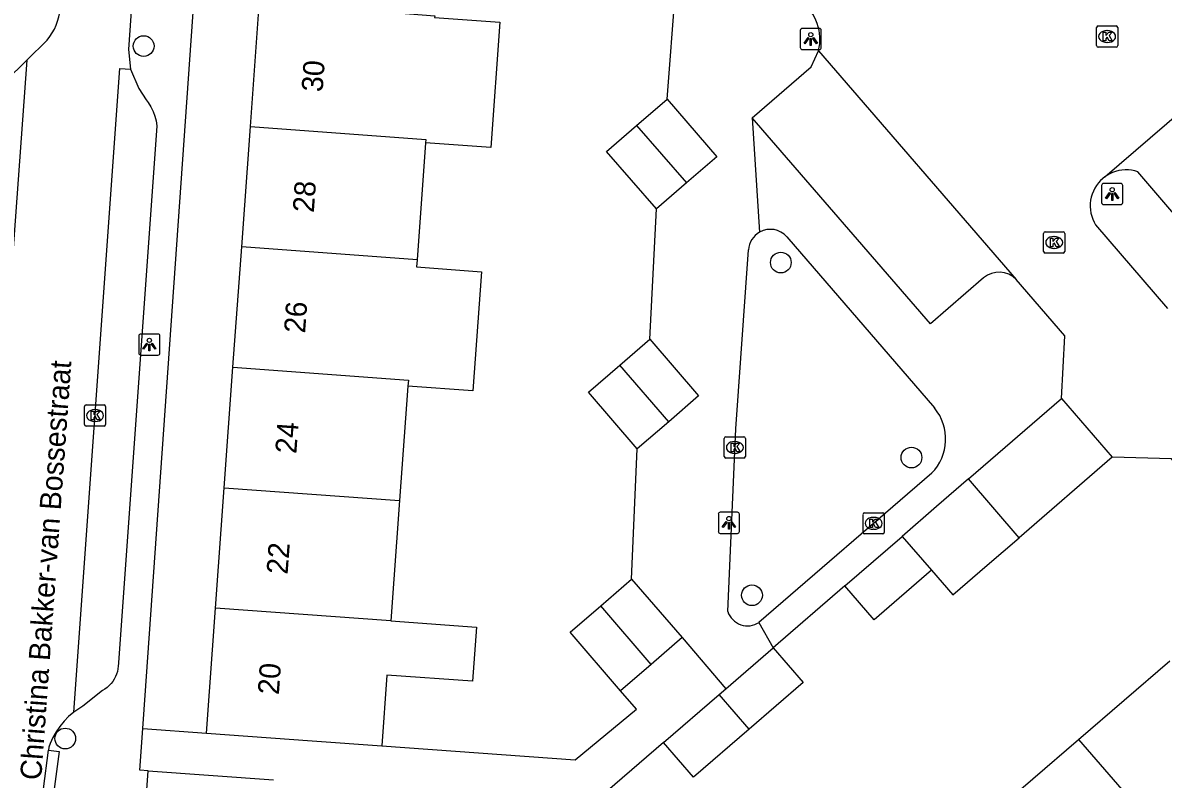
# Model space of a CAD drawing. Extents: x 160304 to 160954, y 383686 to 384161.
# Drawn here: x 160524.6 to 160578.4, y 384061.9 to 384097.6 of the extents above; entities that cross this region are included whole.
import ezdxf

# ---------------------------------------------------------------- set-up
doc = ezdxf.new("R2010")
doc.units = 0
for name, color, linetype in [('IMGEO_Boom', 7, 'Continuous'), ('IMGEO_Kolk', 7, 'Continuous'), ('IMGEO_Lichtpunt', 7, 'Continuous'), ('IMGEO_Openbare_ruimte_label', 7, 'Continuous'), ('IMGEO_Pand', 7, 'Continuous'), ('IMGEO_Pand_nummerreeks', 7, 'Continuous'), ('IMGEO_Rijbaan_lokaal_open', 7, 'Continuous'), ('IMGEO_Voetpad_open', 7, 'Continuous')]:
    doc.layers.add(name, color=color, linetype=linetype)

msp = doc.modelspace()

# ---------------------------------------------------------------- linework, layer by layer
at = {"layer": 'IMGEO_Boom'}
for centre in [(160530.268, 384096.536), (160560.354, 384086.312), (160566.522, 384077.105), (160558.992, 384070.601), (160526.565, 384063.838)]:
    msp.add_circle(centre, 0.489, dxfattribs=at)
at = {"layer": 'IMGEO_Kolk'}
for p, q in [((160575.26, 384096.559), (160575.26, 384097.411)), ((160575.335, 384097.485), (160576.187, 384097.485)), ((160575.748, 384097.265), (160575.773, 384097.265)), ((160576.261, 384097.411), (160576.261, 384096.559)), ((160575.771, 384096.705), (160575.746, 384096.705)), ((160576.187, 384096.485), (160575.335, 384096.485)), ((160572.761, 384086.836), (160572.761, 384087.688)), ((160572.836, 384087.762), (160573.688, 384087.762)), ((160573.249, 384087.542), (160573.274, 384087.542)), ((160573.762, 384087.688), (160573.762, 384086.836)), ((160573.272, 384086.982), (160573.247, 384086.982)), ((160573.688, 384086.762), (160572.836, 384086.762)), ((160527.473, 384078.664), (160527.473, 384079.516)), ((160527.548, 384079.59), (160528.4, 384079.59)), ((160527.961, 384079.37), (160527.986, 384079.37)), ((160528.474, 384079.516), (160528.474, 384078.664)), ((160527.984, 384078.81), (160527.959, 384078.81)), ((160528.4, 384078.59), (160527.548, 384078.59)), ((160557.683, 384077.156), (160557.683, 384078.008)), ((160557.758, 384078.082), (160558.61, 384078.082)), ((160558.171, 384077.862), (160558.196, 384077.862)), ((160558.684, 384078.008), (160558.684, 384077.156)), ((160558.194, 384077.302), (160558.169, 384077.302)), ((160558.61, 384077.082), (160557.758, 384077.082)), ((160564.311, 384074.498), (160565.163, 384074.498)), ((160564.236, 384073.572), (160564.236, 384074.424)), ((160564.724, 384074.278), (160564.749, 384074.278)), ((160565.237, 384074.424), (160565.237, 384073.572)), ((160565.163, 384073.498), (160564.311, 384073.498)), ((160564.747, 384073.718), (160564.722, 384073.718))]:
    msp.add_line(p, q, dxfattribs=at)
for points in [[(160575.26, 384096.559), (160575.26, 384097.411)], [(160575.335, 384097.485), (160576.187, 384097.485)], [(160575.581, 384097.185), (160575.704, 384097.185), (160575.704, 384097.034), (160575.834, 384097.185), (160575.998, 384097.185), (160575.852, 384097.034), (160576.005, 384096.785), (160575.853, 384096.785), (160575.768, 384096.949), (160575.704, 384096.882), (160575.704, 384096.785), (160575.581, 384096.785), (160575.581, 384097.185)], [(160576.261, 384097.411), (160576.261, 384096.559)], [(160576.187, 384096.485), (160575.335, 384096.485)], [(160572.761, 384086.836), (160572.761, 384087.688)], [(160572.836, 384087.762), (160573.688, 384087.762)], [(160573.082, 384087.462), (160573.205, 384087.462), (160573.205, 384087.311), (160573.335, 384087.462), (160573.499, 384087.462), (160573.353, 384087.311), (160573.506, 384087.062), (160573.354, 384087.062), (160573.269, 384087.226), (160573.205, 384087.159), (160573.205, 384087.062), (160573.082, 384087.062), (160573.082, 384087.462)], [(160573.762, 384087.688), (160573.762, 384086.836)], [(160573.688, 384086.762), (160572.836, 384086.762)], [(160527.473, 384078.664), (160527.473, 384079.516)], [(160527.548, 384079.59), (160528.4, 384079.59)], [(160528.474, 384079.516), (160528.474, 384078.664)], [(160527.794, 384079.29), (160527.917, 384079.29), (160527.917, 384079.139), (160528.047, 384079.29), (160528.211, 384079.29), (160528.065, 384079.139), (160528.218, 384078.89), (160528.066, 384078.89), (160527.981, 384079.054), (160527.917, 384078.987), (160527.917, 384078.89), (160527.794, 384078.89), (160527.794, 384079.29)], [(160528.4, 384078.59), (160527.548, 384078.59)], [(160557.683, 384077.156), (160557.683, 384078.008)], [(160557.758, 384078.082), (160558.61, 384078.082)], [(160558.004, 384077.782), (160558.127, 384077.782), (160558.127, 384077.631), (160558.257, 384077.782), (160558.421, 384077.782), (160558.275, 384077.631), (160558.428, 384077.382), (160558.276, 384077.382), (160558.191, 384077.546), (160558.127, 384077.479), (160558.127, 384077.382), (160558.004, 384077.382), (160558.004, 384077.782)], [(160558.684, 384078.008), (160558.684, 384077.156)], [(160558.61, 384077.082), (160557.758, 384077.082)], [(160564.311, 384074.498), (160565.163, 384074.498)], [(160564.236, 384073.572), (160564.236, 384074.424)], [(160564.557, 384074.198), (160564.68, 384074.198), (160564.68, 384074.047), (160564.81, 384074.198), (160564.974, 384074.198), (160564.828, 384074.047), (160564.981, 384073.798), (160564.829, 384073.798), (160564.744, 384073.962), (160564.68, 384073.895), (160564.68, 384073.798), (160564.557, 384073.798), (160564.557, 384074.198)], [(160565.237, 384074.424), (160565.237, 384073.572)], [(160565.163, 384073.498), (160564.311, 384073.498)]]:
    msp.add_lwpolyline(points, dxfattribs=at)
for centre, start, end in [((160575.337, 384097.409), 91.552, 178.448), ((160575.337, 384097.409), 91.552, 178.448), ((160576.185, 384097.409), 1.552, 88.448), ((160576.185, 384097.409), 1.552, 88.448), ((160575.337, 384096.561), 181.552, 268.448), ((160575.337, 384096.561), 181.552, 268.448), ((160576.185, 384096.561), 271.552, 358.448), ((160576.185, 384096.561), 271.552, 358.448), ((160572.838, 384087.686), 91.552, 178.448), ((160572.838, 384087.686), 91.552, 178.448), ((160573.686, 384087.686), 1.552, 88.448), ((160573.686, 384087.686), 1.552, 88.448), ((160572.838, 384086.838), 181.552, 268.448), ((160572.838, 384086.838), 181.552, 268.448), ((160573.686, 384086.838), 271.552, 358.448), ((160573.686, 384086.838), 271.552, 358.448), ((160527.55, 384079.514), 91.552, 178.448), ((160527.55, 384079.514), 91.552, 178.448), ((160528.398, 384079.514), 1.552, 88.448), ((160528.398, 384079.514), 1.552, 88.448), ((160527.55, 384078.666), 181.552, 268.448), ((160527.55, 384078.666), 181.552, 268.448), ((160528.398, 384078.666), 271.552, 358.448), ((160528.398, 384078.666), 271.552, 358.448), ((160557.76, 384078.006), 91.552, 178.448), ((160557.76, 384078.006), 91.552, 178.448), ((160558.608, 384078.006), 1.552, 88.448), ((160558.608, 384078.006), 1.552, 88.448), ((160557.76, 384077.158), 181.552, 268.448), ((160557.76, 384077.158), 181.552, 268.448), ((160558.608, 384077.158), 271.552, 358.448), ((160558.608, 384077.158), 271.552, 358.448), ((160564.313, 384074.422), 91.552, 178.448), ((160564.313, 384074.422), 91.552, 178.448), ((160565.161, 384074.422), 1.552, 88.448), ((160565.161, 384074.422), 1.552, 88.448), ((160564.313, 384073.574), 181.552, 268.448), ((160564.313, 384073.574), 181.552, 268.448), ((160565.161, 384073.574), 271.552, 358.448), ((160565.161, 384073.574), 271.552, 358.448)]:
    msp.add_arc(centre, 0.0765, start, end, dxfattribs=at)
for centre, major_axis, ratio, start_param, end_param in [((160575.747, 384096.985), (-0.387, 0.002), 0.722429, 4.712389, 7.853982), ((160575.772, 384096.985), (-0.39, 0.002), 0.717154, 1.570796, 4.712389), ((160573.248, 384087.262), (-0.387, 0.002), 0.722429, 4.712389, 7.853982), ((160573.273, 384087.262), (-0.39, 0.002), 0.717154, 1.570796, 4.712389), ((160527.96, 384079.09), (-0.387, 0.002), 0.722429, 4.712389, 7.853982), ((160527.985, 384079.09), (-0.39, 0.002), 0.717154, 1.570796, 4.712389), ((160558.17, 384077.582), (-0.387, 0.002), 0.722429, 4.712389, 7.853982), ((160558.195, 384077.582), (-0.39, 0.002), 0.717154, 1.570796, 4.712389), ((160564.723, 384073.998), (-0.387, 0.002), 0.722429, 4.712389, 7.853982), ((160564.748, 384073.998), (-0.39, 0.002), 0.717154, 1.570796, 4.712389)]:
    msp.add_ellipse(centre, major_axis=major_axis, ratio=ratio, start_param=start_param, end_param=end_param, dxfattribs=at)
at = {"layer": 'IMGEO_Lichtpunt'}
for p, q in [((160561.269, 384097.274), (160561.269, 384096.467)), ((160561.269, 384097.274), (160561.269, 384096.467)), ((160562.171, 384097.369), (160561.363, 384097.369)), ((160562.171, 384097.369), (160561.363, 384097.369)), ((160562.265, 384096.467), (160562.265, 384097.274)), ((160562.265, 384096.467), (160562.265, 384097.274)), ((160561.363, 384096.373), (160562.171, 384096.373)), ((160561.363, 384096.373), (160562.171, 384096.373)), ((160575.501, 384089.953), (160575.501, 384089.146)), ((160575.501, 384089.953), (160575.501, 384089.146)), ((160576.403, 384090.048), (160575.595, 384090.048)), ((160576.403, 384090.048), (160575.595, 384090.048)), ((160576.497, 384089.146), (160576.497, 384089.953)), ((160576.497, 384089.146), (160576.497, 384089.953)), ((160575.595, 384089.052), (160576.403, 384089.052)), ((160575.595, 384089.052), (160576.403, 384089.052)), ((160530.04, 384082.844), (160530.04, 384082.037)), ((160530.04, 384082.844), (160530.04, 384082.037)), ((160530.942, 384082.939), (160530.134, 384082.939)), ((160530.942, 384082.939), (160530.134, 384082.939)), ((160531.036, 384082.037), (160531.036, 384082.844)), ((160531.036, 384082.037), (160531.036, 384082.844)), ((160530.134, 384081.943), (160530.942, 384081.943)), ((160530.134, 384081.943), (160530.942, 384081.943)), ((160558.305, 384074.521), (160557.497, 384074.521)), ((160558.305, 384074.521), (160557.497, 384074.521)), ((160557.403, 384074.426), (160557.403, 384073.619)), ((160557.403, 384074.426), (160557.403, 384073.619)), ((160558.399, 384073.619), (160558.399, 384074.426)), ((160558.399, 384073.619), (160558.399, 384074.426)), ((160557.497, 384073.525), (160558.305, 384073.525)), ((160557.497, 384073.525), (160558.305, 384073.525))]:
    msp.add_line(p, q, dxfattribs=at)
for points in [[(160561.643, 384096.938), (160561.682, 384096.91), (160561.494, 384096.648), (160561.456, 384096.675), (160561.643, 384096.938)], [(160561.745, 384096.89), (160561.792, 384096.89), (160561.792, 384096.568), (160561.745, 384096.568), (160561.745, 384096.89)], [(160561.855, 384096.91), (160561.893, 384096.937), (160562.08, 384096.675), (160562.041, 384096.647), (160561.855, 384096.91)], [(160575.875, 384089.617), (160575.914, 384089.589), (160575.726, 384089.327), (160575.688, 384089.354), (160575.875, 384089.617)], [(160575.977, 384089.569), (160576.024, 384089.569), (160576.024, 384089.247), (160575.977, 384089.247), (160575.977, 384089.569)], [(160576.087, 384089.589), (160576.125, 384089.616), (160576.312, 384089.354), (160576.273, 384089.326), (160576.087, 384089.589)], [(160530.414, 384082.508), (160530.453, 384082.48), (160530.265, 384082.218), (160530.227, 384082.245), (160530.414, 384082.508)], [(160530.516, 384082.46), (160530.563, 384082.46), (160530.563, 384082.138), (160530.516, 384082.138), (160530.516, 384082.46)], [(160530.626, 384082.48), (160530.664, 384082.507), (160530.851, 384082.245), (160530.812, 384082.217), (160530.626, 384082.48)], [(160557.777, 384074.09), (160557.816, 384074.062), (160557.628, 384073.8), (160557.59, 384073.827), (160557.777, 384074.09)], [(160557.879, 384074.042), (160557.926, 384074.042), (160557.926, 384073.72), (160557.879, 384073.72), (160557.879, 384074.042)], [(160557.989, 384074.062), (160558.027, 384074.089), (160558.214, 384073.827), (160558.175, 384073.799), (160557.989, 384074.062)]]:
    msp.add_lwpolyline(points, dxfattribs=at)
for centre in [(160561.768, 384097.072), (160576, 384089.751), (160530.539, 384082.642), (160557.902, 384074.224)]:
    msp.add_circle(centre, 0.0994, dxfattribs=at)
for centre, start, end in [((160561.363, 384097.274), 90, 180), ((160561.363, 384097.274), 90, 180), ((160562.171, 384097.274), 0, 90), ((160562.171, 384097.274), 0, 90), ((160561.363, 384096.467), 180, 270), ((160561.363, 384096.467), 180, 270), ((160562.171, 384096.467), 270, 0), ((160562.171, 384096.467), 270, 360), ((160575.595, 384089.953), 90, 180), ((160575.595, 384089.953), 90, 180), ((160576.403, 384089.953), 0, 90), ((160576.403, 384089.953), 0, 90), ((160575.595, 384089.146), 180, 270), ((160575.595, 384089.146), 180, 270), ((160576.403, 384089.146), 270, 0), ((160576.403, 384089.146), 270, 360), ((160530.134, 384082.844), 90, 180), ((160530.134, 384082.844), 90, 180), ((160530.942, 384082.844), 0, 90), ((160530.942, 384082.844), 0, 90), ((160530.134, 384082.037), 180, 270), ((160530.134, 384082.037), 180, 270), ((160530.942, 384082.037), 270, 0), ((160530.942, 384082.037), 270, 360), ((160557.497, 384074.426), 90, 180), ((160557.497, 384074.426), 90, 180), ((160558.305, 384074.426), 0, 90), ((160558.305, 384074.426), 0, 90), ((160557.497, 384073.619), 180, 270), ((160557.497, 384073.619), 180, 270), ((160558.305, 384073.619), 270, 0), ((160558.305, 384073.619), 270, 360)]:
    msp.add_arc(centre, 0.0946, start, end, dxfattribs=at)
at = {"layer": 'IMGEO_Pand'}
for points in [[(160535.311, 384092.74), (160535.71, 384098.248)], [(160541.621, 384098.144), (160544.014, 384097.97), (160544.008, 384097.884), (160547.083, 384097.661), (160546.654, 384091.741), (160543.578, 384091.964)], [(160553.542, 384092.781), (160554.982, 384094.025)], [(160554.982, 384094.025), (160557.328, 384091.308), (160555.899, 384090.074)], [(160554.476, 384088.845), (160552.13, 384091.562), (160553.542, 384092.781)], [(160553.542, 384092.781), (160555.899, 384090.074)], [(160534.898, 384087.058), (160535.311, 384092.74)], [(160535.311, 384092.74), (160543.59, 384092.131), (160543.578, 384091.964)], [(160543.578, 384091.964), (160543.178, 384086.442)], [(160555.899, 384090.074), (160554.476, 384088.845)], [(160534.486, 384081.371), (160534.898, 384087.058)], [(160543.178, 384086.442), (160534.898, 384087.058)], [(160543.178, 384086.442), (160543.157, 384086.103), (160546.216, 384085.882), (160545.808, 384080.251), (160542.745, 384080.473)], [(160552.746, 384081.463), (160554.164, 384082.688)], [(160554.164, 384082.688), (160556.472, 384080.015), (160555.058, 384078.794)], [(160534.073, 384075.671), (160534.486, 384081.371)], [(160534.486, 384081.371), (160542.766, 384080.763), (160542.745, 384080.473)], [(160553.577, 384077.515), (160551.269, 384080.187), (160552.746, 384081.463)], [(160555.058, 384078.794), (160552.746, 384081.463)], [(160542.745, 384080.473), (160542.354, 384075.083)], [(160569.209, 384076.095), (160573.604, 384079.891)], [(160573.604, 384079.891), (160575.999, 384077.117)], [(160555.058, 384078.794), (160553.577, 384077.515)], [(160575.999, 384077.117), (160571.605, 384073.322)], [(160569.209, 384076.095), (160567.7, 384074.792), (160566.086, 384073.383)], [(160571.605, 384073.322), (160569.209, 384076.095)], [(160533.66, 384069.988), (160534.073, 384075.671)], [(160534.073, 384075.671), (160542.354, 384075.083)], [(160542.354, 384075.083), (160541.941, 384069.389)], [(160563.378, 384071.043), (160566.086, 384073.383)], [(160566.086, 384073.383), (160567.462, 384071.789)], [(160567.462, 384071.789), (160568.473, 384070.617), (160570.095, 384072.018), (160571.605, 384073.322)], [(160567.462, 384071.789), (160564.754, 384069.45), (160563.378, 384071.043)], [(160551.854, 384070.104), (160553.309, 384071.36)], [(160553.309, 384071.36), (160555.691, 384068.602)], [(160533.233, 384064.096), (160533.66, 384069.988)], [(160541.941, 384069.389), (160533.66, 384069.988)], [(160552.791, 384066.097), (160550.409, 384068.856), (160551.854, 384070.104)], [(160554.225, 384067.336), (160551.854, 384070.104)], [(160541.941, 384069.389), (160545.981, 384069.097), (160545.796, 384066.543), (160541.756, 384066.836), (160541.514, 384063.495)], [(160555.691, 384068.602), (160554.225, 384067.336)], [(160557.754, 384066.187), (160559.998, 384068.125)], [(160559.998, 384068.125), (160561.414, 384066.485), (160558.864, 384064.283)], [(160574.41, 384063.793), (160578.719, 384067.513)], [(160554.225, 384067.336), (160552.791, 384066.097)], [(160554.82, 384063.652), (160557.438, 384065.914)], [(160557.438, 384065.914), (160557.754, 384066.187)], [(160558.864, 384064.283), (160557.438, 384065.914)], [(160558.864, 384064.283), (160556.236, 384062.013), (160554.82, 384063.652)], [(160533.233, 384064.096), (160538.22, 384063.734), (160541.514, 384063.495)], [(160570.102, 384060.072), (160574.41, 384063.793)], [(160574.41, 384063.793), (160579.845, 384057.535)], [(160530.229, 384058.743), (160530.488, 384062.32)], [(160530.488, 384062.32), (160536.399, 384061.891)]]:
    msp.add_lwpolyline(points, dxfattribs=at)
at = {"layer": 'IMGEO_Rijbaan_lokaal_open'}
for points in [[(160537.481, 384138.035), (160534.196, 384135.168), (160533.788, 384134.809), (160533.414, 384134.416), (160533.076, 384133.99), (160532.778, 384133.536), (160532.521, 384133.058), (160532.308, 384132.558), (160532.141, 384132.041), (160532.021, 384131.511), (160531.948, 384130.973), (160531.927, 384130.626), (160529.545, 384096.378), (160529.643, 384095.449)], [(160575.655, 384090.36), (160587.929, 384100.937)], [(160524.75, 384095.864), (160525.716, 384096.815)], [(160562.131, 384096.314), (160571.467, 384085.506)], [(160524.75, 384095.864), (160522.403, 384063.785)], [(160526.965, 384065.079), (160529.151, 384095.469), (160529.643, 384095.449)], [(160575.655, 384090.36), (160575.452, 384090.185), (160575.35, 384090.073), (160575.259, 384089.951), (160575.178, 384089.823), (160575.11, 384089.687), (160575.054, 384089.546), (160575.011, 384089.401), (160574.981, 384089.252), (160574.964, 384089.101), (160574.961, 384088.949), (160574.971, 384088.798), (160574.995, 384088.648), (160575.033, 384088.501), (160575.083, 384088.358), (160575.146, 384088.22), (160575.218, 384088.092), (160578.615, 384084.142)], [(160573.604, 384079.891), (160573.757, 384082.855), (160571.467, 384085.506)], [(160590.891, 384063.065), (160578.802, 384077.039), (160575.999, 384077.117)], [(160526.965, 384065.079), (160526.727, 384064.877), (160526.509, 384064.654), (160526.311, 384064.412), (160526.136, 384064.154), (160525.984, 384063.882), (160525.858, 384063.596), (160525.798, 384063.432), (160525.778, 384063.283)], [(160525.298, 384059.629), (160525.778, 384063.283)]]:
    msp.add_lwpolyline(points, dxfattribs=at)
for centre, radius, start, end in [((160523.525, 384098.596), 2.824, 320.8869, 354.3452), ((160559.948, 384096.863), 2.251, 345.8903, 52.6046)]:
    msp.add_arc(centre, radius, start, end, dxfattribs=at)
at = {"layer": 'IMGEO_Voetpad_open'}
for points in [[(160530.227, 384064.308), (160532.622, 384098.352), (160530.921, 384098.428), (160533.173, 384130.684), (160533.182, 384130.784), (160533.255, 384131.273), (160533.37, 384131.754), (160533.529, 384132.222), (160533.728, 384132.674), (160533.967, 384133.107), (160534.244, 384133.516), (160534.556, 384133.899), (160534.901, 384134.253), (160548.216, 384145.882), (160548.855, 384146.134)], [(160587.929, 384100.937), (160590.827, 384097.546), (160579.575, 384087.85), (160577.208, 384090.597), (160577.062, 384090.64), (160576.914, 384090.669), (160576.763, 384090.685), (160576.611, 384090.688), (160576.46, 384090.677), (160576.31, 384090.652), (160576.163, 384090.615), (160576.02, 384090.564), (160575.882, 384090.501), (160575.75, 384090.425), (160575.655, 384090.36)], [(160554.982, 384094.025), (160555.383, 384099.177)], [(160559.002, 384093.154), (160561.779, 384095.553), (160562.131, 384096.314)], [(160523.578, 384094.74), (160523.746, 384094.883), (160524.75, 384095.864)], [(160529.643, 384095.449), (160530.04, 384094.53), (160530.394, 384094.002), (160530.485, 384093.872), (160530.607, 384093.667), (160530.71, 384093.451), (160530.793, 384093.227), (160530.856, 384092.997), (160530.898, 384092.762), (160529.075, 384067.418), (160529.076, 384067.391), (160529.071, 384067.261), (160529.056, 384067.132), (160529.028, 384067.005), (160528.99, 384066.881), (160528.94, 384066.761), (160528.88, 384066.645), (160528.81, 384066.536), (160528.731, 384066.433), (160528.642, 384066.338), (160528.546, 384066.251), (160528.442, 384066.172), (160528.331, 384066.104), (160527.396, 384065.366), (160526.965, 384065.079)], [(160569.927, 384085.584), (160567.416, 384083.414), (160559.002, 384093.154)], [(160559.002, 384093.154), (160559.351, 384087.746)], [(160554.164, 384082.688), (160554.476, 384088.845)], [(160560.637, 384087.524), (160567.613, 384079.447)], [(160557.847, 384069.834), (160558.223, 384078.458), (160558.834, 384086.916)], [(160553.309, 384071.36), (160553.577, 384077.515)], [(160567.476, 384076.364), (160559.323, 384069.323)], [(160563.378, 384071.043), (160559.998, 384068.125)], [(160559.323, 384069.323), (160559.998, 384068.125)], [(160555.691, 384068.602), (160557.754, 384066.187)], [(160541.514, 384063.495), (160550.645, 384062.832), (160553.546, 384065.222), (160552.791, 384066.097)], [(160530.488, 384062.32), (160530.089, 384062.351), (160530.227, 384064.308)], [(160530.227, 384064.308), (160533.233, 384064.096)], [(160525.778, 384063.283), (160526.273, 384063.218), (160525.793, 384059.564), (160525.298, 384059.629)], [(160554.82, 384063.652), (160551.361, 384060.677), (160549.71, 384060.797)]]:
    msp.add_lwpolyline(points, dxfattribs=at)
for centre, radius, start, end in [((160559.855, 384086.856), 1.023, 119.5216, 176.6416), ((160559.859, 384086.855), 1.026, 40.7187, 119.6927), ((160570.657, 384084.751), 1.108, 42.9841, 131.2168), ((160565.816, 384077.982), 2.318, 315.7286, 39.1827), ((160558.78, 384070.14), 0.982, 198.1915, 303.6162)]:
    msp.add_arc(centre, radius, start, end, dxfattribs=at)

# ---------------------------------------------------------------- texts
at = {"layer": 'IMGEO_Openbare_ruimte_label'}
msp.add_text('Christina Bakker-van Bossestraat', height=1, rotation=85.8695, dxfattribs=at).set_placement((160525.427, 384061.851))
at = {"layer": 'IMGEO_Pand_nummerreeks'}
for s, rotation, p in [('30', 85.852, (160538.715, 384094.343)), ('28', 85.852, (160538.302, 384088.651)), ('26', 85.852, (160537.889, 384082.956)), ('24', 85.852, (160537.476, 384077.264)), ('22', 85.8517, (160537.064, 384071.569)), ('20', 85.8517, (160536.651, 384065.883))]:
    msp.add_text(s, height=1, rotation=rotation, dxfattribs=at).set_placement(p)

doc.saveas('drawing.dxf')
